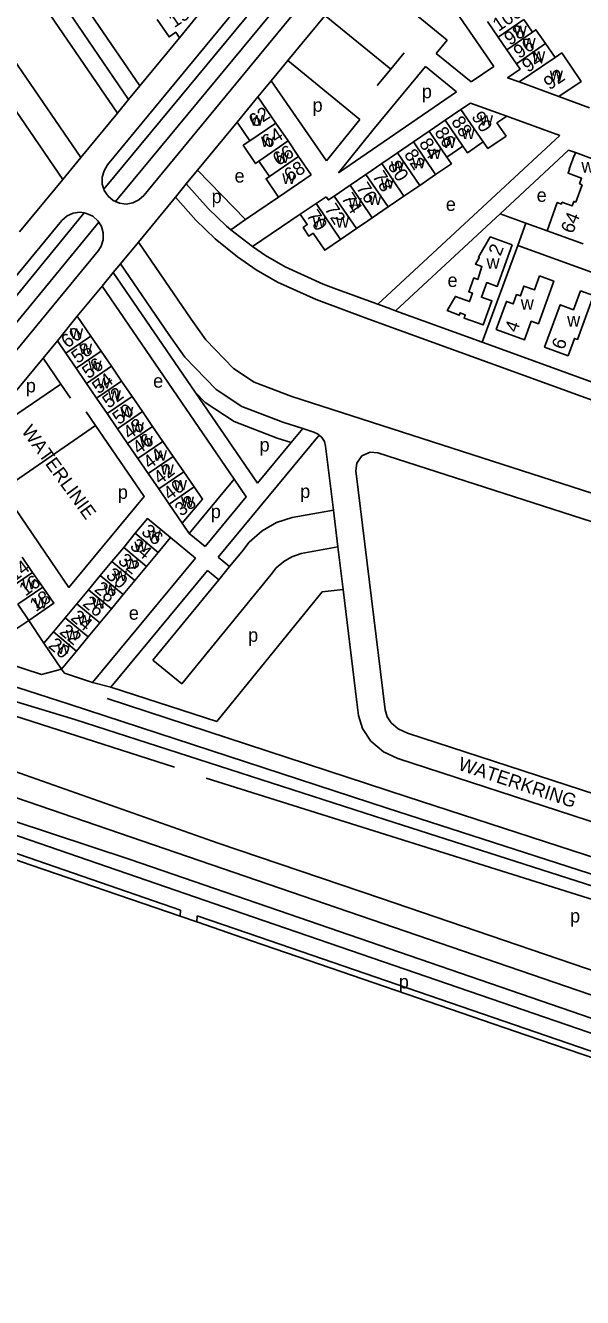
# Model space of a CAD drawing. Extents: x 154320 to 156262, y 382651 to 384180.
# Drawn here: x 155553.7 to 155718.2, y 382657.3 to 383033.1 of the extents above; entities that cross this region are included whole.
import ezdxf

# ---------------------------------------------------------------- set-up
doc = ezdxf.new("R2010")
doc.units = 0
for name, color, linetype in [('BLT_Basislijn', 7, 'Continuous'), ('BLT_Bebouwing', 7, 'Continuous'), ('BLT_Centroide', 7, 'Continuous'), ('BLT_Gemeentegrens', 7, 'Continuous'), ('BLT_Huisnummer', 7, 'Continuous'), ('BLT_Huisnummer_ tussenligend', 7, 'Continuous'), ('BLT_Onderverdeling_panden', 7, 'Continuous'), ('BLT_Straatnaam', 7, 'Continuous'), ('BLT_Vlakafsluiter', 7, 'Continuous')]:
    doc.layers.add(name, color=color, linetype=linetype)

msp = doc.modelspace()

# ---------------------------------------------------------------- linework, layer by layer
at = {"layer": 'BLT_Basislijn'}
for p, q in [((155577.92, 382991.91), (155699.45, 383139.48)), ((155588.6, 382982.86), (155707.89, 383127.77)), ((155550.93, 383059.84), (155584.13, 383011.26)), ((155555.06, 383062.66), (155587.44, 383015.29)), ((155691.94, 383020.97), (155663.69, 383062.31)), ((155517.73, 383056.31), (155564.68, 382987.63)), ((155545.57, 383058.83), (155580.83, 383007.24)), ((155533.04, 383048.1), (155569.98, 382994.07)), ((155631.15, 383022.79), (155653.07, 383049.4)), ((155642.42, 383035.73), (155661.52, 383020.19)), ((155587.44, 383015.29), (155599.14, 383029.51)), ((155626.23, 383016.81), (155631.15, 383022.79)), ((155661.52, 383020.19), (155665.46, 383025)), ((155674.97, 383024.86), (155685.3, 383016.43)), ((155661.52, 383020.19), (155657.51, 383015.36)), ((155671.79, 383021), (155680.99, 383013.49)), ((155685.3, 383016.43), (155691.94, 383020.97)), ((155584.13, 383011.26), (155587.44, 383015.29)), ((155622.29, 383012.03), (155626.23, 383016.81)), ((155642.54, 382993.15), (155626.23, 383016.81)), ((155580.83, 383007.24), (155584.13, 383011.26)), ((155646.09, 382989.59), (155680.99, 383013.49)), ((155711.2, 383012.17), (155720.26, 383008.83)), ((155569.98, 382994.07), (155580.83, 383007.24)), ((155604.51, 382990.4), (155616.18, 383004.59)), ((155652.42, 383005.34), (155642.54, 382993.15)), ((155695.82, 383006.36), (155711.44, 383000.64)), ((155656.29, 383002.17), (155646.09, 382989.59)), ((155711.44, 383000.64), (155657.69, 382950.74)), ((155693.85, 382977.49), (155714.06, 382996.26)), ((155716.11, 382995.54), (155714.06, 382996.26)), ((155601.17, 382986.33), (155604.51, 382990.4)), ((155604.51, 382990.4), (155618.67, 382975.75)), ((155551.92, 382972.12), (155564.68, 382987.63)), ((155597.95, 382982.42), (155601.17, 382986.33)), ((155587.02, 382969.14), (155597.95, 382982.42)), ((155628.4, 382982.43), (155618.67, 382975.75)), ((155571.04, 382977.72), (155493.33, 382883.01)), ((155634.8, 382977.32), (155620.7, 382967.79)), ((155490.16, 382885.35), (155564.44, 382975.53)), ((155575.3, 382975.04), (155497.24, 382879.9)), ((155618.67, 382975.75), (155614.31, 382972.76)), ((155614.31, 382972.76), (155620.7, 382967.79)), ((155707.68, 382972.41), (155701.45, 382974.72)), ((155501, 382876.48), (155575.24, 382966.64)), ((155699.06, 382968.15), (155688.54, 382939.53)), ((155579.59, 382960.11), (155581.72, 382962.71)), ((155576.28, 382956.09), (155579.59, 382960.11)), ((155568.96, 382947.2), (155576.28, 382956.09)), ((155657.69, 382950.74), (155661.46, 382949.37)), ((155661.46, 382949.37), (155662.97, 382948.82)), ((155655.02, 382946.39), (155754.06, 382910.42)), ((155558.88, 382934.84), (155563.09, 382939.93)), ((155688.54, 382939.53), (155755.76, 382915.12)), ((155538.78, 382910.52), (155558.88, 382934.84)), ((155539.09, 382910.05), (155564.14, 382927.16)), ((155574.39, 382914.89), (155546.87, 382895.92)), ((155610.56, 382875.98), (155613.94, 382873.23)), ((155607.38, 382872.13), (155610.77, 382869.36)), ((155651.52, 382833.16), (155647.46, 382866.52)), ((155559.14, 382850.58), (155554.67, 382857.36)), ((155511.04, 382850.51), (155566.62, 382832.56)), ((155599.8, 382838.61), (155591.31, 382845.56)), ((155507.93, 382842.69), (155597.71, 382813.99)), ((155573.5, 382839), (155578.86, 382837.63)), ((155566.62, 382832.56), (155660.5, 382801.9)), ((155568.29, 382828.1), (155659.76, 382798.56)), ((155607.07, 382810.69), (155732.73, 382771.2)), ((155659.76, 382798.56), (155922.4, 382714.29)), ((155599.44, 382771.77), (155599.33, 382769.95)), ((155604.35, 382770.08), (155604.23, 382768.27)), ((155628.37, 382771.61), (155937.44, 382665.23))]:
    msp.add_line(p, q, dxfattribs=at)
for points in [[(155707.05, 383141.17), (155696.56, 383129.57), (155576.82, 382984.73)], [(155710.74, 383137.8), (155700.35, 383126.3), (155580.3, 382981.1)], [(155678.17, 383028.75), (155653.07, 383049.4)], [(155674.97, 383024.86), (155678.17, 383028.75)], [(155631.15, 383022.79), (155652.42, 383005.34)], [(155656.29, 383002.17), (155671.79, 383021)], [(155577.92, 382991.91), (155576.86, 382990.21), (155576.31, 382988.28), (155576.33, 382986.28), (155576.82, 382984.73)], [(155576.82, 382984.73), (155576.93, 382984.38), (155578.04, 382982.71), (155579.57, 382981.42), (155580.3, 382981.1)], [(155601.17, 382986.33), (155607.57, 382979.01), (155613, 382973.81), (155614.31, 382972.76)], [(155580.3, 382981.1), (155581.4, 382980.62), (155583.38, 382980.36), (155585.35, 382980.69), (155587.16, 382981.56), (155588.6, 382982.86)], [(155597.95, 382982.42), (155603.95, 382975.55), (155609.7, 382970.05), (155616.3, 382964.75), (155621.83, 382960.95), (155628.06, 382957.31), (155639.52, 382952.14), (155655.02, 382946.39)], [(155564.44, 382975.53), (155565.95, 382976.83), (155567.78, 382977.64), (155569.76, 382977.92), (155571.04, 382977.72)], [(155571.04, 382977.72), (155571.74, 382977.61), (155573.55, 382976.75), (155575.05, 382975.43), (155575.3, 382975.04)], [(155693.85, 382977.49), (155662.97, 382948.82)], [(155701.45, 382974.72), (155693.85, 382977.49)], [(155575.3, 382975.04), (155576.12, 382973.74), (155576.65, 382971.82), (155576.63, 382969.82), (155576.05, 382967.9), (155575.24, 382966.64)], [(155701.45, 382974.72), (155699.06, 382968.15)], [(155587.02, 382969.14), (155602.57, 382946.39), (155606.93, 382940.2), (155615.08, 382931.77), (155621.24, 382927.71), (155632.33, 382923.49), (155936.55, 382825.44)], [(155620.7, 382967.79), (155624.51, 382965.17), (155630.35, 382961.76), (155641.58, 382956.69)], [(155699.06, 382968.15), (155758.28, 382946.61)], [(155581.72, 382962.71), (155595.99, 382941.83), (155600.74, 382935.08), (155609.94, 382925.58), (155617.57, 382920.54), (155629.68, 382915.94), (155635.55, 382914.05)], [(155603.74, 382924.8), (155579.59, 382960.11)], [(155615.3, 382899.04), (155576.28, 382956.09)], [(155641.58, 382956.69), (155645.5, 382955.17), (155657.69, 382950.74)], [(155662.97, 382948.82), (155688.54, 382939.53)], [(155564.14, 382927.16), (155558.88, 382934.84)], [(155566.96, 382923.04), (155564.14, 382927.16)], [(155622.16, 382897.86), (155603.74, 382924.8)], [(155603.74, 382924.8), (155606.73, 382921.71), (155615.28, 382916.07), (155628.02, 382911.22), (155632.12, 382909.9)], [(155574.39, 382914.89), (155571.57, 382919.01)], [(155546.87, 382895.92), (155566.51, 382867.1), (155588.7, 382893.95), (155574.39, 382914.89)], [(155632.12, 382909.9), (155635.55, 382914.05)], [(155635.55, 382914.05), (155638.87, 382912.98)], [(155638.87, 382912.98), (155640.12, 382912.37), (155640.42, 382912.1)], [(155610.56, 382875.98), (155640.42, 382912.1)], [(155622.16, 382897.86), (155632.12, 382909.9)], [(155640.42, 382912.1), (155641.19, 382911.4), (155641.94, 382910.17), (155642.3, 382908.83)], [(155644.6, 382889.95), (155642.3, 382908.83)], [(155657.74, 382906.9), (155655.44, 382907.08), (155653.03, 382905.99), (155651.51, 382903.83), (155651.25, 382901.53)], [(155657.74, 382906.9), (155933.28, 382818.09), (155939.34, 382814.58), (155944.23, 382809.86), (155948.06, 382804.8), (155950.79, 382799.64), (155952.77, 382794.44), (155952.85, 382794.13)], [(155879.92, 382754.47), (155666.53, 382824.04), (155663.74, 382825.35), (155661.67, 382827.07), (155660.51, 382828.82), (155659.85, 382830.96), (155651.25, 382901.53)], [(155602.05, 382882.99), (155615.3, 382899.04)], [(155606.69, 382879.15), (155618.85, 382893.85), (155615.3, 382899.04)], [(155523.87, 382892.37), (155549.96, 382854.2), (155554.67, 382857.36)], [(155644.6, 382889.95), (155632.39, 382887.74), (155627.81, 382886.23), (155623.52, 382883.77), (155619.7, 382880.43), (155617.54, 382877.63), (155613.94, 382873.23)], [(155645.93, 382879.04), (155644.6, 382889.95)], [(155599.97, 382886.05), (155602.05, 382882.99)], [(155602.05, 382882.99), (155606.69, 382879.15)], [(155603.84, 382875.7), (155596.51, 382881.81)], [(155645.93, 382879.04), (155635.1, 382877.08), (155632.31, 382876.16), (155629.92, 382874.79), (155627.72, 382872.87), (155626.13, 382870.8), (155599.8, 382838.61)], [(155647.46, 382866.52), (155645.93, 382879.04)], [(155573.5, 382839), (155603.84, 382875.7)], [(155577.78, 382834.26), (155666.41, 382805.25), (155910.27, 382725.89), (155935.24, 382723.45), (155956.97, 382730.17), (155974.93, 382743.23), (155985.37, 382757.44), (156061.48, 382871.71)], [(155578.86, 382837.63), (155607.38, 382872.13)], [(155613.94, 382873.23), (155610.77, 382869.36)], [(155610.77, 382869.36), (155591.31, 382845.56)], [(155578.86, 382837.63), (155610.14, 382827.47), (155641.25, 382865.78), (155647.46, 382866.52)], [(155507.14, 382857.77), (155509.86, 382857.17), (155558.41, 382841.39), (155564.32, 382842.97)], [(155507.06, 382846.63), (155568.29, 382828.1)], [(155564.32, 382842.97), (155565.21, 382841.73), (155573.5, 382839)], [(155904.79, 382737.95), (155663.58, 382816.59), (155659.42, 382818.54), (155655.64, 382821.67), (155653.2, 382825.37), (155652, 382829.28), (155651.52, 382833.16)], [(155948.42, 382657.28), (155882.54, 382679.83), (155796.3, 382709.35), (155620.98, 382769.65), (155540.38, 382797.4), (155532.14, 382800.46), (155523.11, 382804.65), (155513.94, 382809.54), (155508.52, 382813.15), (155501.43, 382818.72), (155495.6, 382824.35), (155490.07, 382829.62)], [(155599.44, 382771.77), (155538.69, 382792.69), (155530.22, 382795.85), (155524.94, 382798.29), (155506.1, 382808.68), (155488.6, 382824.12)], [(155953.32, 382666.86), (155533.99, 382810.75), (155524.14, 382815.11)], [(155535.2, 382818.08), (155610.54, 382791.49), (155658.83, 382775.14)], [(155526.44, 382805.92), (155584.54, 382786.66), (155628.37, 382771.61)], [(155660.5, 382801.9), (155864.45, 382736.03), (155916.83, 382718.75)], [(155658.83, 382775.14), (155851.64, 382709.27), (155948.03, 382675.83)], [(155745.36, 382721.59), (155619.35, 382764.92), (155604.35, 382770.08)]]:
    msp.add_lwpolyline(points, dxfattribs=at)
at = {"layer": 'BLT_Bebouwing'}
for p, q in [((155599.14, 383029.51), (155605.27, 383036.94)), ((155690.12, 383034.3), (155693.27, 383029.7)), ((155700.81, 383034.93), (155703.43, 383031.15)), ((155693.27, 383029.7), (155695.86, 383025.9)), ((155695.86, 383025.9), (155698.65, 383021.8)), ((155710.07, 383023.68), (155707.24, 383027.75)), ((155622.29, 383012.03), (155616.18, 383004.59)), ((155627.6, 383004.26), (155622.29, 383012.03)), ((155682.28, 383008.32), (155677.57, 383005.1)), ((155631.2, 382999), (155627.6, 383004.26)), ((155677.57, 383005.1), (155672.89, 383001.9)), ((155672.89, 383001.9), (155668.21, 382998.7)), ((155634.33, 382994.42), (155631.2, 382999)), ((155663.54, 382995.51), (155658.86, 382992.31)), ((155668.21, 382998.7), (155663.54, 382995.51)), ((155723.5, 382992.86), (155716.11, 382995.54)), ((155658.86, 382992.31), (155654.18, 382989.12)), ((155654.18, 382989.12), (155649.51, 382985.92)), ((155670.11, 382985.88), (155674.79, 382989.08)), ((155649.51, 382985.92), (155644.83, 382982.73)), ((155665.44, 382982.69), (155670.11, 382985.88)), ((155718.04, 382986.04), (155716.18, 382980.91)), ((155717.28, 382986.31), (155718.04, 382986.04)), ((155660.76, 382979.49), (155665.44, 382982.69)), ((155656.08, 382976.3), (155660.76, 382979.49)), ((155646.73, 382969.91), (155651.41, 382973.1)), ((155654.76, 382975.39), (155656.08, 382976.3)), ((155707.68, 382972.41), (155718.31, 382968.6)), ((155568.96, 382947.2), (155563.09, 382939.93)), ((155576.02, 382936.88), (155572.97, 382941.34)), ((155565.6, 382936.27), (155568.64, 382931.82)), ((155579.06, 382932.44), (155576.02, 382936.88)), ((155568.64, 382931.82), (155571.68, 382927.37)), ((155582.07, 382928.05), (155579.06, 382932.44)), ((155585.15, 382923.54), (155582.07, 382928.05)), ((155571.68, 382927.37), (155574.69, 382922.98)), ((155574.69, 382922.98), (155577.78, 382918.47)), ((155588.25, 382919.02), (155585.15, 382923.54)), ((155577.78, 382918.47), (155580.87, 382913.95)), ((155591.22, 382914.68), (155588.25, 382919.02)), ((155580.87, 382913.95), (155583.84, 382909.61)), ((155594.27, 382910.22), (155591.22, 382914.68)), ((155583.84, 382909.61), (155586.89, 382905.15)), ((155597.29, 382905.81), (155594.27, 382910.22)), ((155586.89, 382905.15), (155589.91, 382900.74)), ((155600.39, 382901.28), (155597.29, 382905.81)), ((155589.91, 382900.74), (155593.01, 382896.21)), ((155603.46, 382896.79), (155600.39, 382901.28)), ((155593.01, 382896.21), (155596.09, 382891.72)), ((155582.67, 382878.93), (155586.11, 382883.08)), ((155579.22, 382874.78), (155582.67, 382878.93)), ((155555.76, 382871.54), (155552.71, 382875.99)), ((155592.88, 382877.43), (155589.44, 382873.28)), ((155558.77, 382867.13), (155555.76, 382871.54)), ((155575.77, 382870.62), (155579.22, 382874.78)), ((155589.44, 382873.28), (155585.99, 382869.12)), ((155572.27, 382866.4), (155575.77, 382870.62)), ((155585.99, 382869.12), (155582.55, 382864.96)), ((155568.84, 382862.27), (155572.27, 382866.4)), ((155582.55, 382864.96), (155579.05, 382860.74)), ((155565.41, 382858.13), (155568.84, 382862.27)), ((155579.05, 382860.74), (155575.62, 382856.61)), ((155561.94, 382853.96), (155565.41, 382858.13)), ((155575.62, 382856.61), (155572.22, 382852.5))]:
    msp.add_line(p, q, dxfattribs=at)
for points in [[(155592.54, 383034.92), (155596.07, 383029.75), (155598.07, 383031.12), (155599.14, 383029.51)], [(155703.43, 383031.15), (155704.42, 383031.83), (155707.24, 383027.75)], [(155698.65, 383021.8), (155699.74, 383020.21), (155696.03, 383017.68), (155699.45, 383016.44)], [(155711.2, 383012.17), (155717.73, 383016.59), (155712.03, 383025.02), (155710.07, 383023.68)], [(155699.45, 383016.44), (155711.2, 383012.17)], [(155685.05, 383010.21), (155682.28, 383008.32)], [(155695.82, 383006.36), (155685.05, 383010.21)], [(155616.18, 383004.59), (155619.94, 382999.07)], [(155695.6, 383000.39), (155692.89, 383004.35), (155695.82, 383006.36)], [(155619.94, 382999.07), (155617.96, 382997.72), (155621.62, 382992.33), (155622.63, 382993.03)], [(155688.87, 382998.71), (155690.23, 382996.72), (155695.6, 383000.39)], [(155678.1, 382994.25), (155682.8, 382997.48)], [(155682.8, 382997.48), (155684.16, 382995.49), (155688.87, 382998.71)], [(155716.11, 382995.54), (155715.79, 382994.66), (155715.71, 382994.69), (155714.25, 382990.65)], [(155622.63, 382993.03), (155625.71, 382988.49)], [(155638.02, 382989.01), (155634.33, 382994.42)], [(155674.79, 382989.08), (155679.46, 382992.27), (155678.1, 382994.25)], [(155625.71, 382988.49), (155624.73, 382987.82), (155628.4, 382982.43)], [(155628.4, 382982.43), (155638.02, 382989.01)], [(155714.25, 382990.65), (155714.33, 382990.62), (155713.91, 382989.45), (155717.9, 382988), (155717.28, 382986.31)], [(155639.49, 382980.51), (155634.8, 382977.32)], [(155642.45, 382982.53), (155639.49, 382980.51)], [(155644.83, 382982.73), (155643.13, 382981.56), (155642.45, 382982.53)], [(155712.1, 382980.88), (155711.92, 382980.36), (155710.68, 382980.8), (155707.68, 382972.41)], [(155716.18, 382980.91), (155715.59, 382981.12), (155715.11, 382979.79), (155712.1, 382980.88)], [(155634.8, 382977.32), (155636.89, 382974.27), (155635.64, 382973.4), (155637.34, 382970.89), (155638.6, 382971.75), (155642.05, 382966.71), (155646.73, 382969.91)], [(155651.41, 382973.1), (155654.76, 382975.39)], [(155572.97, 382941.34), (155568.96, 382947.2)], [(155563.09, 382939.93), (155565.6, 382936.27)], [(155599.97, 382886.05), (155605.93, 382893.19), (155603.46, 382896.79)], [(155596.09, 382891.72), (155599.97, 382886.05)], [(155586.11, 382883.08), (155589.73, 382887.44), (155596.51, 382881.81)], [(155596.51, 382881.81), (155592.88, 382877.43)], [(155554.67, 382857.36), (155562.02, 382862.39), (155558.77, 382867.13)], [(155551.45, 382862.1), (155554.67, 382857.36)], [(155559.14, 382850.58), (155561.94, 382853.96)], [(155572.22, 382852.5), (155568.73, 382848.29)], [(155564.32, 382842.97), (155559.14, 382850.58)], [(155568.73, 382848.29), (155564.32, 382842.97)]]:
    msp.add_lwpolyline(points, dxfattribs=at)
for points in [[(155697.39, 382968.32), (155690.94, 382970.63), (155687.42, 382964.62), (155687.67, 382964.57), (155687.63, 382964.49), (155686.54, 382962.64), (155688.47, 382961.91), (155687.23, 382958.1), (155686.11, 382958.53), (155684.55, 382954.46), (155685.64, 382954.04), (155684.8, 382951.52), (155680.65, 382953.08), (155678.23, 382948.93), (155681.75, 382947.52), (155682, 382948.22), (155683.52, 382947.67), (155683.17, 382946.68), (155688.87, 382944.63), (155691.42, 382951.73), (155688.33, 382952.84), (155689.88, 382957.15), (155692.97, 382956.04)], [(155705.47, 382959.12), (155709.69, 382957.59), (155705.13, 382944.98), (155703.05, 382945.73), (155701.08, 382940.28), (155692.71, 382943.31), (155695.7, 382951.59), (155697.69, 382950.87), (155698.68, 382953.6), (155699.81, 382953.19), (155700.87, 382956.11), (155703.96, 382954.99)], [(155717.53, 382954.75), (155721.43, 382953.34), (155716.72, 382940.34), (155715.79, 382940.68), (155713.92, 382935.55), (155706.97, 382938.09), (155711.57, 382950.61), (155715.47, 382949.11)]]:
    msp.add_lwpolyline(points, close=True, dxfattribs=at)
at = {"layer": 'BLT_Gemeentegrens'}
for points in [[(155599.33, 382769.95), (155555.4, 382785.05), (155536.23, 382791.64), (155533.79, 382792.58)], [(155604.23, 382768.27), (155599.33, 382769.95)], [(155744.04, 382720.22), (155742.3, 382720.81), (155730.39, 382724.91), (155701.48, 382734.84), (155637.36, 382756.88), (155620.4, 382762.71), (155604.23, 382768.27)]]:
    msp.add_lwpolyline(points, dxfattribs=at)
at = {"layer": 'BLT_Onderverdeling_panden'}
for p, q in [((155693.27, 383029.7), (155700.81, 383034.93)), ((155703.43, 383031.15), (155695.86, 383025.9)), ((155698.65, 383021.8), (155707.24, 383027.75)), ((155699.45, 383016.44), (155710.07, 383023.68)), ((155688.87, 382998.71), (155682.28, 383008.32)), ((155619.94, 382999.07), (155627.6, 383004.26)), ((155677.57, 383005.1), (155682.8, 382997.48)), ((155678.1, 382994.25), (155672.89, 383001.9)), ((155622.63, 382993.03), (155631.2, 382999)), ((155670.11, 382985.88), (155663.54, 382995.51)), ((155668.21, 382998.7), (155674.79, 382989.08)), ((155658.86, 382992.31), (155665.44, 382982.69)), ((155660.76, 382979.49), (155654.18, 382989.12)), ((155649.51, 382985.92), (155656.08, 382976.3)), ((155639.49, 382980.51), (155646.73, 382969.91)), ((155651.41, 382973.1), (155644.83, 382982.73)), ((155565.6, 382936.27), (155572.97, 382941.34)), ((155568.64, 382931.82), (155576.02, 382936.88)), ((155571.68, 382927.37), (155579.06, 382932.44)), ((155574.69, 382922.98), (155582.07, 382928.05)), ((155577.78, 382918.47), (155585.15, 382923.54)), ((155580.87, 382913.95), (155588.25, 382919.02)), ((155583.84, 382909.61), (155591.22, 382914.68)), ((155586.89, 382905.15), (155594.27, 382910.22)), ((155589.91, 382900.74), (155597.29, 382905.81)), ((155593.01, 382896.21), (155600.39, 382901.28)), ((155596.09, 382891.72), (155603.46, 382896.79)), ((155586.11, 382883.08), (155592.88, 382877.43)), ((155582.67, 382878.93), (155589.44, 382873.28)), ((155548.44, 382866.52), (155555.76, 382871.54)), ((155579.22, 382874.78), (155585.99, 382869.12)), ((155575.77, 382870.62), (155582.55, 382864.96)), ((155551.45, 382862.1), (155558.77, 382867.13)), ((155572.27, 382866.4), (155579.05, 382860.74)), ((155568.84, 382862.27), (155575.62, 382856.61)), ((155565.41, 382858.13), (155572.22, 382852.5)), ((155561.94, 382853.96), (155568.73, 382848.29))]:
    msp.add_line(p, q, dxfattribs=at)
msp.add_lwpolyline([(155625.71, 382988.49), (155625.71, 382988.49), (155634.33, 382994.42)], dxfattribs=at)
at = {"layer": 'BLT_Vlakafsluiter'}
for p, q in [((155564.68, 382987.63), (155569.98, 382994.07)), ((155581.72, 382962.71), (155587.02, 382969.14))]:
    msp.add_line(p, q, dxfattribs=at)

# ---------------------------------------------------------------- texts
at = {"layer": 'BLT_Centroide'}
for s, p in [('w', (155697.85, 383030.02)), ('w', (155700.46, 383026.36)), ('w', (155703.28, 383022.4)), ('w', (155708.5, 383016.65)), ('p', (155670.72, 383011.63)), ('p', (155638.45, 383007.62)), ('w', (155620.01, 383003.55)), ('w', (155687.88, 383003.53)), ('w', (155623.24, 382997.18)), ('w', (155676.85, 382996.96)), ('w', (155682.46, 382999.53)), ('w', (155627.62, 382992.48)), ('w', (155672.5, 382993.62)), ('w', (155661.59, 382989.94)), ('w', (155667.89, 382990.86)), ('w', (155717.83, 382989.67)), ('e', (155615.41, 382986.71)), ('w', (155629.5, 382986.32)), ('w', (155658.61, 382984.91)), ('p', (155608.64, 382980.63)), ('w', (155649.11, 382979.06)), ('w', (155654.96, 382980.1)), ('e', (155677.8, 382978.33)), ('w', (155638.47, 382973.42)), ('w', (155645.36, 382973.42)), ('w', (155689.82, 382961.23)), ('w', (155699.93, 382949.14)), ('w', (155713.62, 382944.16)), ('w', (155566.82, 382940.52)), ('w', (155569.48, 382936.08)), ('w', (155572.25, 382930.98)), ('p', (155553.77, 382924.72)), ('w', (155574.91, 382925.88)), ('e', (155591.38, 382926.11)), ('w', (155578.01, 382922.28)), ('w', (155581.65, 382917.29)), ('w', (155584.79, 382912.8)), ('w', (155587.38, 382908.8)), ('p', (155622.8, 382907.25)), ('w', (155591.58, 382904.49)), ('w', (155593.61, 382900.39)), ('w', (155597.49, 382895.73)), ('p', (155580.94, 382893.26)), ('w', (155599.6, 382890.85)), ('p', (155634.8, 382893.51)), ('p', (155608.39, 382887.54)), ('w', (155589.75, 382880.92)), ('w', (155585.81, 382877.58)), ('w', (155583.1, 382872.49)), ('w', (155579.77, 382868.94)), ('w', (155552.71, 382866.48)), ('w', (155576.78, 382864.84)), ('w', (155556.26, 382860.93)), ('w', (155573.35, 382860.85)), ('e', (155584.19, 382857.55)), ('w', (155569.14, 382855.86)), ('w', (155565.59, 382851.42)), ('p', (155619.43, 382851.03)), ('w', (155563.04, 382847.43)), ('p', (155714.48, 382768.08)), ('p', (155663.91, 382748.6))]:
    msp.add_text(s, height=4, dxfattribs=at).set_placement(p)
for p in [(155704.61, 382981.03), (155678.29, 382955.87)]:
    msp.add_text('e', height=4, rotation=359.5, dxfattribs=at).set_placement(p)
at = {"layer": 'BLT_Huisnummer'}
for s, rotation, p in [('155', 34.3538, (155597.65, 383032.3)), ('100', 34.3538, (155693.36, 383031.19)), ('98', 34.3538, (155696.75, 383027.05)), ('96', 34.3538, (155699.5, 383023.14)), ('94', 34.3538, (155702.04, 383019.06)), ('92', 34.3538, (155708.43, 383013.9)), ('62', 33, (155621.26, 383002.79)), ('90', 303, (155685.21, 383006.16)), ('86', 303, (155674.3, 383001.57)), ('66', 33, (155628.33, 382991.49)), ('82', 303, (155665.33, 382995.02)), ('68', 33, (155631.68, 382986.78)), ('78', 303, (155655.96, 382988.53)), ('74', 303, (155646.77, 382982.08)), ('70', 303, (155636.49, 382977.04)), ('64', 68.284, (155715.3, 382971.39)), ('2', 68.284, (155693.92, 382964.79)), ('60', 36.8685, (155566.08, 382937.61)), ('4', 70.0195, (155698.8, 382942.18)), ('6', 70.0181, (155712.66, 382937.09)), ('56', 36.8685, (155572.28, 382928.54)), ('52', 36.8685, (155578.26, 382919.81)), ('48', 36.8685, (155584.37, 382910.64)), ('44', 36.8685, (155590.3, 382901.88)), ('40', 36.8685, (155596.24, 382892.65)), ('38', 36.8685, (155599.67, 382887.91)), ('36', 320.3099, (155587.62, 382883.09)), ('14', 36.8685, (155550.51, 382868.73)), ('32', 320.3099, (155580.73, 382874.51)), ('28', 320.3099, (155573.76, 382866.17)), ('18', 36.8685, (155556.8, 382859.75)), ('24', 320.3099, (155566.75, 382857.73)), ('20', 320.3099, (155560.13, 382849.55))]:
    msp.add_text(s, height=4, rotation=rotation, dxfattribs=at).set_placement(p)
at = {"layer": 'BLT_Huisnummer_ tussenligend'}
for s, rotation, p in [('64', 33, (155625.12, 382996.63)), ('88', 303, (155679.25, 383004.73)), ('84', 303, (155669.72, 382998.26)), ('80', 303, (155660.49, 382991.63)), ('76', 303, (155651.24, 382985.13)), ('72', 303, (155641.84, 382978.9)), ('58', 36.8685, (155569.1, 382933.04)), ('54', 36.8685, (155575.22, 382924.04)), ('50', 36.8685, (155581.26, 382914.98)), ('46', 36.8685, (155587.12, 382906.21)), ('42', 36.8685, (155593.34, 382897.32)), ('34', 320.3099, (155584.26, 382878.88)), ('30', 320.3099, (155577.18, 382870.25)), ('16', 36.8685, (155553.69, 382864.32)), ('26', 320.3099, (155570.3, 382861.92)), ('22', 320.3099, (155563.45, 382853.6))]:
    msp.add_text(s, height=4, rotation=rotation, dxfattribs=at).set_placement(p)
at = {"layer": 'BLT_Straatnaam'}
for s, rotation, p in [('WATERLINIE', 306.0883, (155552.33, 382913.24)), ('WATERKRING', 341.6818, (155681.15, 382813.29))]:
    msp.add_text(s, height=4, rotation=rotation, dxfattribs=at).set_placement(p)

doc.saveas('drawing.dxf')
